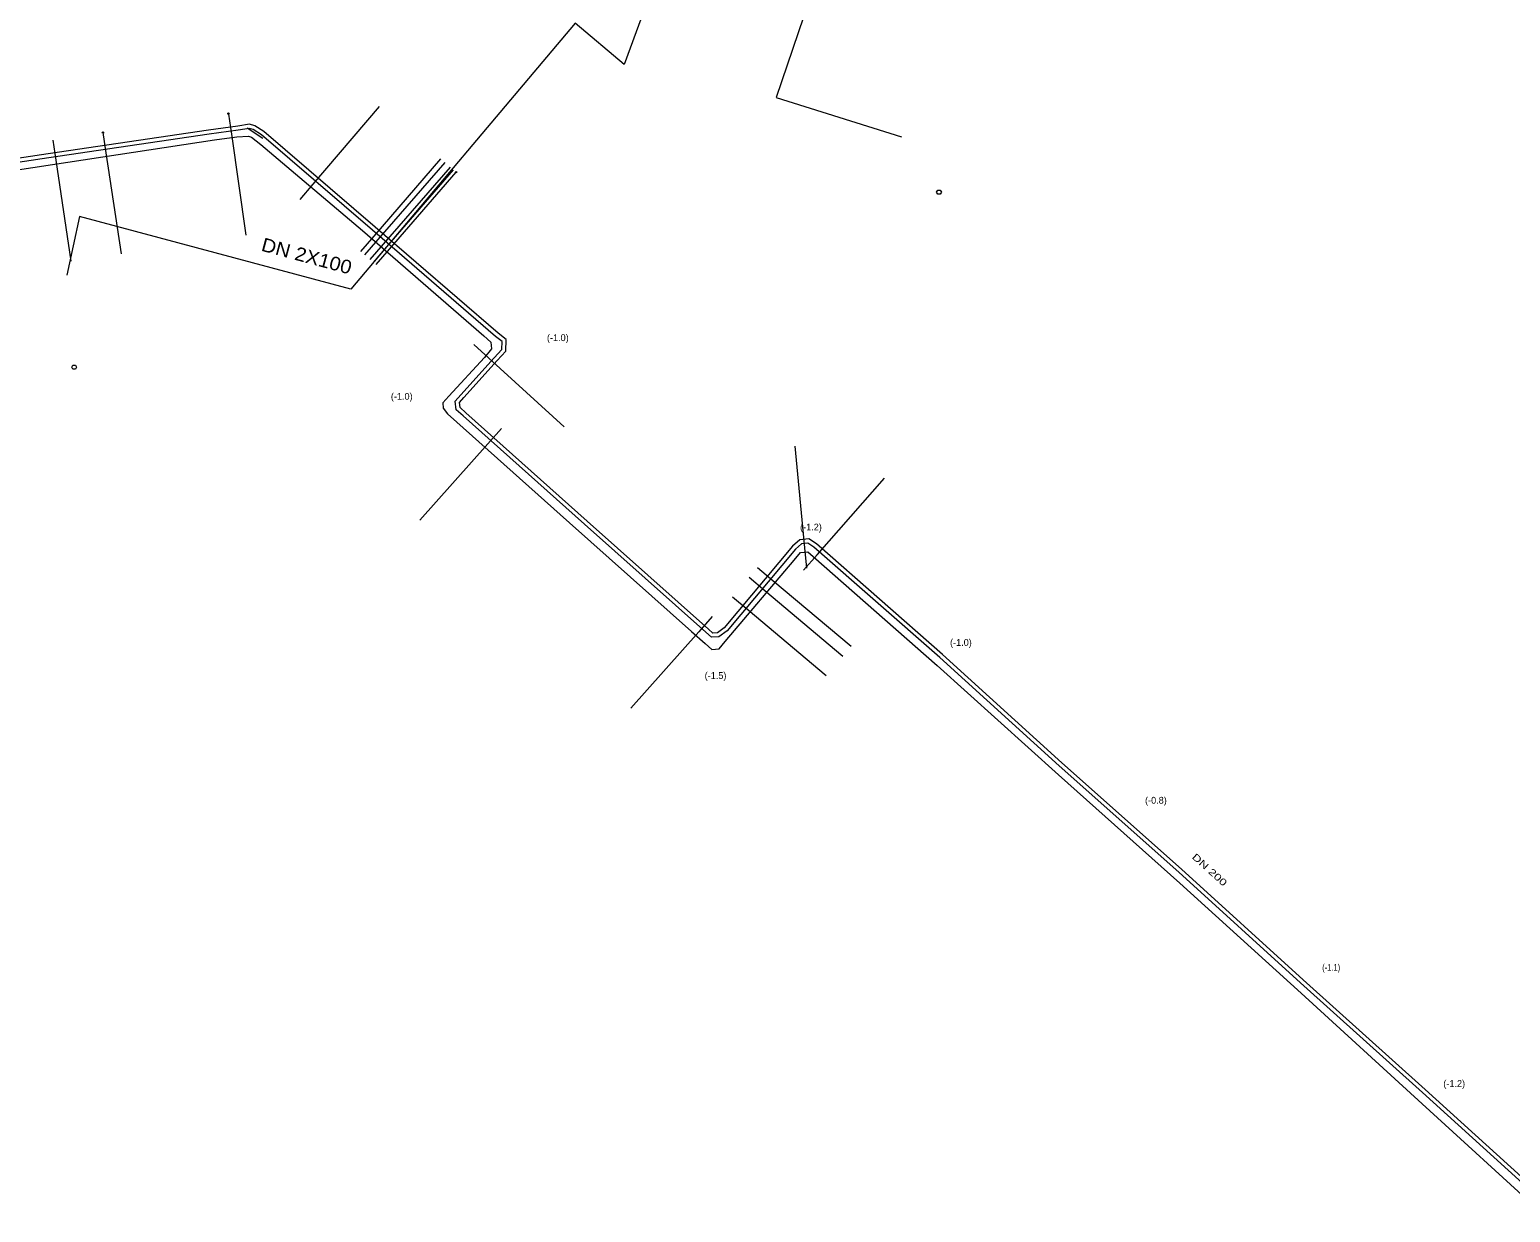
# Model space of a CAD drawing. Extents: x -725606 to -725269, y -977352 to -977136.
# Drawn here: x -725544.1 to -725435.3, y -977310.1 to -977223.1 of the extents above; entities that cross this region are included whole.
import ezdxf
from ezdxf.enums import TextEntityAlignment as Align

# ---------------------------------------------------------------- set-up
doc = ezdxf.new("R2010")
doc.units = 0
doc.header["$LTSCALE"] = 0.2
doc.header["$PDMODE"] = 32
doc.header["$PDSIZE"] = 0.1
for name, color, linetype, lineweight in [('45', 7, 'Continuous', 13), ('47', 7, 'Continuous', 13), ('48', 7, 'Continuous', 13), ('63', 7, 'Continuous', 13)]:
    doc.layers.add(name, color=color, linetype=linetype, lineweight=lineweight)
doc.layers.add('46', color=7, linetype='Continuous')

msp = doc.modelspace()

# ---------------------------------------------------------------- linework, layer by layer
at = {"layer": '45'}
for points in [[(-725518.81, -977240.24), (-725517.83, -977239.11), (-725512.92, -977233.44)], [(-725518.62, -977240.41), (-725517.64, -977239.28), (-725512.73, -977233.61)]]:
    msp.add_lwpolyline(points, dxfattribs=at)
msp.add_point((-725512.73, -977233.61), dxfattribs=at)
at = {"layer": '47'}
msp.add_line((-725528.08, -977230.36), (-725526.93, -977231.12), dxfattribs=at)
for points in [[(-725524.2, -977235.63), (-725523.23, -977234.49), (-725518.36, -977228.78)], [(-725538.69, -977230.7), (-725538.47, -977232.19), (-725537.36, -977239.61)], [(-725519.04, -977240.04), (-725518.06, -977238.91), (-725513.15, -977233.24)], [(-725511.44, -977246.27), (-725510.33, -977247.28), (-725504.79, -977252.34)], [(-725509.4, -977252.46), (-725510.4, -977253.58), (-725515.39, -977259.18)], [(-725487.2, -977262.87), (-725486.21, -977261.75), (-725481.26, -977256.11)], [(-725491.21, -977263.38), (-725490.06, -977264.35), (-725484.32, -977269.18)], [(-725490.6, -977262.66), (-725489.45, -977263.63), (-725483.71, -977268.46)]]:
    msp.add_lwpolyline(points, dxfattribs=at)
at = {"layer": '48'}
for points in [[(-725529.45, -977229.34), (-725529.24, -977230.83), (-725528.18, -977238.25)], [(-725542.37, -977231.26), (-725542.15, -977232.74), (-725541.04, -977240.16)], [(-725519.74, -977239.44), (-725518.76, -977238.31), (-725513.85, -977232.64)], [(-725519.44, -977239.7), (-725518.46, -977238.57), (-725513.55, -977232.9)], [(-725486.97, -977262.71), (-725487.11, -977261.22), (-725487.82, -977253.75)], [(-725492.42, -977264.82), (-725491.27, -977265.79), (-725485.53, -977270.62)], [(-725493.91, -977266.28), (-725494.91, -977267.4), (-725499.9, -977273)]]:
    msp.add_lwpolyline(points, dxfattribs=at)
for p in [(-725529.47, -977229.31), (-725538.69, -977230.7)]:
    msp.add_point(p, dxfattribs=at)
at = {"layer": '63'}
for points in [[(-725501.45, -977169.48), (-725499.84, -977170.93), (-725501.11, -977172.33), (-725485.83, -977186.1), (-725491.16, -977200.54), (-725500.38, -977225.7), (-725503.99, -977222.67), (-725520.46, -977242.21), (-725540.4, -977236.86), (-725541.34, -977241.18)], [(-725474.68, -977184.79), (-725480.68, -977202.29), (-725485.17, -977216.21), (-725489.21, -977228.12), (-725480, -977231.01)], [(-725512.439, -977250.92), (-725512.493, -977250.545), (-725512.167, -977250.18), (-725509.708, -977247.452), (-725509.072, -977246.759), (-725509.058, -977245.919), (-725509.638, -977245.45), (-725518.684, -977237.643), (-725526.853, -977230.617), (-725527.528, -977230.203), (-725527.91, -977230.094), (-725528.783, -977230.223), (-725530.933, -977230.533), (-725542.704, -977232.253), (-725554.765, -977234.073)], [(-725512.72, -977251.07), (-725512.81, -977250.45), (-725512.39, -977249.98), (-725509.93, -977247.25), (-725509.37, -977246.64), (-725509.36, -977246.06), (-725509.83, -977245.68), (-725518.88, -977237.87), (-725527.03, -977230.86), (-725527.65, -977230.48), (-725527.93, -977230.4), (-725528.74, -977230.52), (-725530.89, -977230.83), (-725542.66, -977232.55), (-725554.72, -977234.37)], [(-725554.3, -977234.85), (-725542.4, -977233.05), (-725530.49, -977231.24), (-725528.84, -977231.01), (-725527.99, -977230.96), (-725527.77, -977231.04), (-725527.09, -977231.57), (-725519.61, -977237.9), (-725510.7, -977245.64), (-725510.18, -977246.11), (-725510.13, -977246.59), (-725510.66, -977247.24), (-725513.27, -977250.07), (-725513.7, -977250.56), (-725513.69, -977250.96), (-725513.36, -977251.38), (-725504.4, -977259.38), (-725495.44, -977267.37), (-725494.44, -977268.26), (-725493.95, -977268.7), (-725493.4, -977268.64), (-725492.97, -977268.12), (-725487.89, -977262.12), (-725487.43, -977261.57), (-725486.89, -977261.51), (-725486.49, -977261.87), (-725477.39, -977269.88), (-725468.48, -977277.9), (-725459.55, -977285.86), (-725450.63, -977293.95), (-725441.74, -977302.1), (-725433.01, -977310.07)], [(-725432.8, -977309.35), (-725441.73, -977301.26), (-725450.69, -977293.2), (-725459.63, -977285.06), (-725468.42, -977277.24), (-725477.2, -977269.28), (-725486.44, -977261.18), (-725486.89, -977260.88), (-725487.36, -977260.92), (-725487.79, -977261.31), (-725492.82, -977267.32), (-725493.42, -977267.77), (-725493.97, -977267.8), (-725494.38, -977267.43), (-725503.3, -977259.48), (-725512.21, -977251.53), (-725512.72, -977251.07)], [(-725432.599, -977309.127), (-725441.529, -977301.037), (-725450.489, -977292.978), (-725459.429, -977284.837), (-725468.22, -977277.017), (-725477, -977269.056), (-725486.257, -977260.941), (-725486.811, -977260.572), (-725487.486, -977260.63), (-725488.007, -977261.102), (-725493.028, -977267.101), (-725493.527, -977267.475), (-725493.862, -977267.494), (-725494.18, -977267.207), (-725503.1, -977259.256), (-725512.01, -977251.307), (-725512.439, -977250.92)]]:
    msp.add_lwpolyline(points, dxfattribs=at)
for points in [[(-725477.158, -977234.939), (-725477.068, -977235.089), (-725477.158, -977235.239), (-725477.338, -977235.239), (-725477.428, -977235.089), (-725477.338, -977234.939)], [(-725540.712, -977247.804), (-725540.622, -977247.954), (-725540.712, -977248.104), (-725540.892, -977248.104), (-725540.982, -977247.954), (-725540.892, -977247.804)]]:
    msp.add_lwpolyline(points, close=True, dxfattribs=at)

# ---------------------------------------------------------------- texts
at = {"layer": '46'}
for s, p in [('(-1.0)', (-725505.26, -977246.03)), ('(-1.0)', (-725516.73, -977250.34)), ('(-1.2)', (-725486.66, -977259.95)), ('(-1.0)', (-725475.64, -977268.43)), ('(-1.5)', (-725493.67, -977270.86)), ('(-0.8)', (-725461.31, -977280.03)), ('(-1.2)', (-725439.39, -977300.85))]:
    msp.add_text(s, height=0.5, dxfattribs=at).set_placement(p, align=Align.CENTER)
at = {"layer": '46', "width": 0.8}
msp.add_text('(-1.1)', height=0.5, dxfattribs=at).set_placement((-725448.43, -977292.31), align=Align.CENTER)
at = {"layer": '63'}
for s, height, rotation, width, p in [('DN 2X100', 1, 344.978, 1.1, (-725523.8421, -977240.2541)), ('DN 200', 0.5, 317.705, 1.4, (-725457.5312, -977285.0736))]:
    msp.add_text(s, height=height, rotation=rotation, dxfattribs=dict(at, width=width)).set_placement(p, align=Align.CENTER)

doc.saveas('drawing.dxf')
